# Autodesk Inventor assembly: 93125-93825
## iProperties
Author: Administrator
Shininess: 64.0
Angle Display Precision: 2
Document Length Units: 11272
Document Angle Units: 11286
Document Time Units: 11279
Document Mass Units: 11290
Document Length Units Precision: 3
Document Angle Units Precision: 2
Compacted: True
PropertySet Name: _Private Model Information
Created: 2002-03
Part Number: 93125-93825
Document SubType Name: Assembly
Designer: Administrator
Control State: 0
Master: False
Checked Out: False
PropertySet Name: Design Tracking Control
Density: 0.0
Volumn: 0.0
Area: 0.0
PropertySet Name: Model Information
